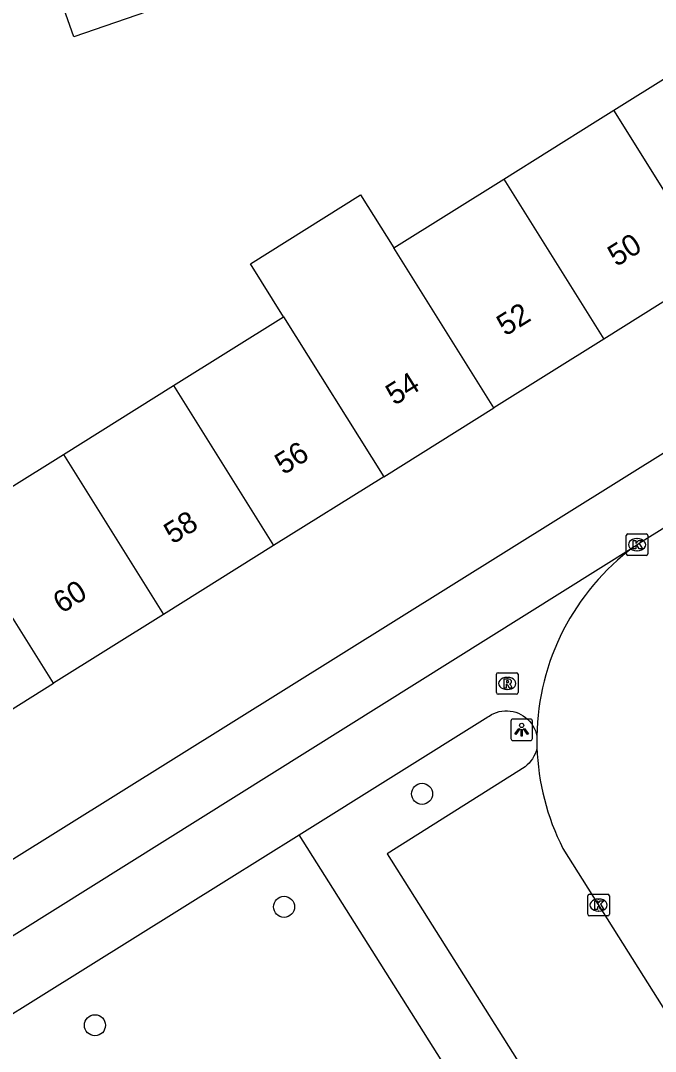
# Model space of a CAD drawing. Extents: x 160077 to 160945, y 386481 to 387498.
# Drawn here: x 160202.38 to 160231.86, y 387206.82 to 387254.7 of the extents above; entities that cross this region are included whole.
import ezdxf

# ---------------------------------------------------------------- set-up
doc = ezdxf.new("R2010")
doc.units = 0
for name, color, linetype in [('IMGEO_Boom', 7, 'Continuous'), ('IMGEO_Fietspad_open', 7, 'Continuous'), ('IMGEO_Kolk', 7, 'Continuous'), ('IMGEO_Lichtpunt', 7, 'Continuous'), ('IMGEO_Pand', 7, 'Continuous'), ('IMGEO_Pand_nummerreeks', 7, 'Continuous'), ('IMGEO_Rijbaan_lokaal_open', 7, 'Continuous'), ('IMGEO_Rioolput', 7, 'Continuous'), ('IMGEO_Voetpad_open', 7, 'Continuous')]:
    doc.layers.add(name, color=color, linetype=linetype)

msp = doc.modelspace()

# ---------------------------------------------------------------- linework, layer by layer
at = {"layer": 'IMGEO_Boom'}
for centre in [(160221.024, 387218.784), (160214.615, 387213.534), (160205.833, 387208.034)]:
    msp.add_circle(centre, 0.489, dxfattribs=at)
at = {"layer": 'IMGEO_Fietspad_open'}
for points in [[(160183.16, 387200.334), (160188.403, 387203.609), (160190.744, 387205.097), (160192.259, 387206.087), (160230.858, 387230.252)], [(160215.32, 387216.878), (160224.07, 387222.353), (160224.134, 387222.398), (160224.245, 387222.465), (160224.362, 387222.522), (160224.482, 387222.567), (160224.607, 387222.602), (160224.734, 387222.626), (160224.863, 387222.638), (160224.992, 387222.639), (160225.121, 387222.628), (160225.248, 387222.606), (160225.373, 387222.572), (160225.495, 387222.527), (160225.611, 387222.472), (160225.723, 387222.406), (160225.828, 387222.331), (160225.926, 387222.247), (160226.016, 387222.154), (160226.098, 387222.053), (160226.17, 387221.946), (160226.232, 387221.833), (160226.284, 387221.714), (160226.325, 387221.592), (160226.355, 387221.466)], [(160184.423, 387197.569), (160192.529, 387202.664), (160211.947, 387214.771), (160215.32, 387216.878)]]:
    msp.add_lwpolyline(points, dxfattribs=at)
at = {"layer": 'IMGEO_Kolk'}
for p, q in [((160230.582, 387230.858), (160231.434, 387230.858)), ((160230.507, 387229.932), (160230.507, 387230.784)), ((160230.995, 387230.638), (160231.02, 387230.638)), ((160231.508, 387230.784), (160231.508, 387229.932)), ((160231.434, 387229.858), (160230.582, 387229.858)), ((160231.018, 387230.078), (160230.993, 387230.078)), ((160228.72, 387213.19), (160228.72, 387214.042)), ((160228.795, 387214.116), (160229.647, 387214.116)), ((160229.721, 387214.042), (160229.721, 387213.19)), ((160229.208, 387213.896), (160229.233, 387213.896)), ((160229.647, 387213.116), (160228.795, 387213.116)), ((160229.231, 387213.336), (160229.206, 387213.336))]:
    msp.add_line(p, q, dxfattribs=at)
for points in [[(160230.582, 387230.858), (160231.434, 387230.858)], [(160230.507, 387229.932), (160230.507, 387230.784)], [(160230.828, 387230.558), (160230.951, 387230.558), (160230.951, 387230.407), (160231.081, 387230.558), (160231.245, 387230.558), (160231.099, 387230.407), (160231.252, 387230.158), (160231.1, 387230.158), (160231.015, 387230.322), (160230.951, 387230.255), (160230.951, 387230.158), (160230.828, 387230.158), (160230.828, 387230.558)], [(160231.508, 387230.784), (160231.508, 387229.932)], [(160231.434, 387229.858), (160230.582, 387229.858)], [(160228.72, 387213.19), (160228.72, 387214.042)], [(160228.795, 387214.116), (160229.647, 387214.116)], [(160229.721, 387214.042), (160229.721, 387213.19)], [(160229.041, 387213.816), (160229.164, 387213.816), (160229.164, 387213.665), (160229.294, 387213.816), (160229.458, 387213.816), (160229.312, 387213.665), (160229.465, 387213.416), (160229.313, 387213.416), (160229.228, 387213.58), (160229.164, 387213.513), (160229.164, 387213.416), (160229.041, 387213.416), (160229.041, 387213.816)], [(160229.647, 387213.116), (160228.795, 387213.116)]]:
    msp.add_lwpolyline(points, dxfattribs=at)
for centre, start, end in [((160230.584, 387230.782), 91.552, 178.448), ((160230.584, 387230.782), 91.552, 178.448), ((160231.432, 387230.782), 1.552, 88.448), ((160231.432, 387230.782), 1.552, 88.448), ((160230.584, 387229.934), 181.552, 268.448), ((160230.584, 387229.934), 181.552, 268.448), ((160231.432, 387229.934), 271.552, 358.448), ((160231.432, 387229.934), 271.552, 358.448), ((160228.797, 387214.04), 91.552, 178.448), ((160228.797, 387214.04), 91.552, 178.448), ((160229.645, 387214.04), 1.552, 88.448), ((160229.645, 387214.04), 1.552, 88.448), ((160228.797, 387213.192), 181.552, 268.448), ((160228.797, 387213.192), 181.552, 268.448), ((160229.645, 387213.192), 271.552, 358.448), ((160229.645, 387213.192), 271.552, 358.448)]:
    msp.add_arc(centre, 0.0765, start, end, dxfattribs=at)
for centre, major_axis, ratio, start_param, end_param in [((160230.994, 387230.358), (-0.387, 0.002), 0.722429, 4.712389, 7.853982), ((160231.019, 387230.358), (-0.39, 0.002), 0.717154, 1.570796, 4.712389), ((160229.207, 387213.616), (-0.387, 0.002), 0.722429, 4.712389, 7.853982), ((160229.232, 387213.616), (-0.39, 0.002), 0.717154, 1.570796, 4.712389)]:
    msp.add_ellipse(centre, major_axis=major_axis, ratio=ratio, start_param=start_param, end_param=end_param, dxfattribs=at)
at = {"layer": 'IMGEO_Lichtpunt'}
for p, q in [((160226.052, 387222.257), (160225.244, 387222.257)), ((160226.052, 387222.257), (160225.244, 387222.257)), ((160225.15, 387222.162), (160225.15, 387221.355)), ((160225.15, 387222.162), (160225.15, 387221.355)), ((160226.146, 387221.355), (160226.146, 387222.162)), ((160226.146, 387221.355), (160226.146, 387222.162)), ((160225.244, 387221.261), (160226.052, 387221.261)), ((160225.244, 387221.261), (160226.052, 387221.261))]:
    msp.add_line(p, q, dxfattribs=at)
for points in [[(160225.524, 387221.826), (160225.563, 387221.798), (160225.375, 387221.536), (160225.337, 387221.563), (160225.524, 387221.826)], [(160225.626, 387221.778), (160225.673, 387221.778), (160225.673, 387221.456), (160225.626, 387221.456), (160225.626, 387221.778)], [(160225.736, 387221.798), (160225.774, 387221.825), (160225.961, 387221.563), (160225.922, 387221.535), (160225.736, 387221.798)]]:
    msp.add_lwpolyline(points, dxfattribs=at)
msp.add_circle((160225.649, 387221.96), 0.0994, dxfattribs=at)
for centre, start, end in [((160225.244, 387222.162), 90, 180), ((160225.244, 387222.162), 90, 180), ((160226.052, 387222.162), 0, 90), ((160226.052, 387222.162), 0, 90), ((160225.244, 387221.355), 180, 270), ((160225.244, 387221.355), 180, 270), ((160226.052, 387221.355), 270, 0), ((160226.052, 387221.355), 270, 360)]:
    msp.add_arc(centre, 0.0946, start, end, dxfattribs=at)
at = {"layer": 'IMGEO_Pand'}
for points in [[(160208.715, 387255.288), (160204.855, 387253.942), (160204.036, 387256.29)], [(160229.929, 387250.541), (160235.042, 387253.739)], [(160224.817, 387247.344), (160229.064, 387250), (160229.929, 387250.541)], [(160234.579, 387243.107), (160230.268, 387250), (160229.929, 387250.541)], [(160219.705, 387244.147), (160224.817, 387247.344)], [(160224.817, 387247.344), (160229.466, 387239.91)], [(160214.592, 387240.949), (160213.055, 387243.407), (160218.168, 387246.605), (160219.705, 387244.147)], [(160224.355, 387236.713), (160219.705, 387244.147)], [(160234.579, 387243.107), (160229.466, 387239.91)], [(160209.48, 387237.751), (160214.592, 387240.949)], [(160214.592, 387240.949), (160219.242, 387233.515)], [(160229.466, 387239.91), (160224.355, 387236.713)], [(160204.367, 387234.554), (160209.48, 387237.751)], [(160209.48, 387237.751), (160214.129, 387230.317)], [(160219.242, 387233.515), (160224.355, 387236.713)], [(160199.255, 387231.356), (160204.367, 387234.554)], [(160204.367, 387234.554), (160209.017, 387227.119)], [(160219.242, 387233.515), (160214.129, 387230.317)], [(160203.904, 387223.922), (160199.255, 387231.356)], [(160214.129, 387230.317), (160209.017, 387227.119)], [(160209.017, 387227.119), (160203.904, 387223.922)], [(160198.595, 387220.601), (160203.904, 387223.922)]]:
    msp.add_lwpolyline(points, dxfattribs=at)
at = {"layer": 'IMGEO_Rijbaan_lokaal_open'}
for points in [[(160242.323, 387237.407), (160231.101, 387230.415), (160230.944, 387230.31), (160230.858, 387230.252)], [(160226.355, 387221.466), (160226.36, 387220.948)], [(160227.566, 387216.245), (160250.335, 387180.106), (160272.691, 387144.583)]]:
    msp.add_lwpolyline(points, dxfattribs=at)
for centre, radius, start, end in [((160237.513, 387221.294), 11.159, 126.6099, 179.118), ((160237.468, 387221.29), 11.114, 181.7657, 206.9994)]:
    msp.add_arc(centre, radius, start, end, dxfattribs=at)
at = {"layer": 'IMGEO_Rioolput'}
for p, q in [((160224.477, 387223.485), (160224.477, 387224.337)), ((160224.552, 387224.411), (160225.404, 387224.411)), ((160224.965, 387224.191), (160224.99, 387224.191)), ((160225.478, 387224.337), (160225.478, 387223.485)), ((160224.988, 387223.631), (160224.963, 387223.631)), ((160225.404, 387223.411), (160224.552, 387223.411))]:
    msp.add_line(p, q, dxfattribs=at)
for points in [[(160224.477, 387223.485), (160224.477, 387224.337)], [(160224.552, 387224.411), (160225.404, 387224.411)], [(160225.066, 387224.109), (160224.814, 387224.111), (160224.814, 387223.711)], [(160225.478, 387224.337), (160225.478, 387223.485)], [(160224.814, 387223.711), (160224.938, 387223.711), (160224.938, 387223.873), (160224.949, 387223.873)], [(160224.992, 387224.03), (160224.938, 387224.03), (160224.938, 387223.949)], [(160224.938, 387223.949), (160224.99, 387223.949)], [(160224.996, 387223.844), (160225.067, 387223.711), (160225.207, 387223.711), (160225.142, 387223.837)], [(160225.404, 387223.411), (160224.552, 387223.411)]]:
    msp.add_lwpolyline(points, dxfattribs=at)
for centre, radius, start, end in [((160224.554, 387224.335), 0.0765, 91.552, 178.448), ((160224.554, 387224.335), 0.0765, 91.552, 178.448), ((160225.065, 387223.999), 0.109, 350.3612, 89.416), ((160225.402, 387224.335), 0.0765, 1.552, 88.448), ((160225.402, 387224.335), 0.0765, 1.552, 88.448), ((160224.948, 387223.82), 0.0533, 26.0293, 88.6989), ((160224.974, 387224.138), 0.19, 274.7715, 282.9687), ((160224.998, 387223.934), 0.0964, 77.0061, 93.1865), ((160225.012, 387223.991), 0.0378, 276.6634, 79.6772), ((160225.063, 387223.999), 0.112, 277.5842, 350.9817), ((160225.047, 387223.784), 0.108, 29.5134, 73.7905), ((160224.554, 387223.487), 0.0765, 181.552, 268.448), ((160224.554, 387223.487), 0.0765, 181.552, 268.448), ((160225.402, 387223.487), 0.0765, 271.552, 358.448), ((160225.402, 387223.487), 0.0765, 271.552, 358.448)]:
    msp.add_arc(centre, radius, start, end, dxfattribs=at)
for centre, major_axis, ratio, start_param, end_param in [((160224.964, 387223.911), (-0.387, 0.002), 0.722429, 4.712389, 7.853982), ((160224.989, 387223.911), (-0.39, 0.002), 0.717154, 1.570796, 4.712389)]:
    msp.add_ellipse(centre, major_axis=major_axis, ratio=ratio, start_param=start_param, end_param=end_param, dxfattribs=at)
at = {"layer": 'IMGEO_Voetpad_open'}
for points in [[(160201.816, 387215.631), (160253.275, 387247.762)], [(160226.36, 387220.948), (160226.349, 387220.891), (160226.316, 387220.766), (160226.273, 387220.645), (160226.218, 387220.528), (160226.154, 387220.417), (160226.08, 387220.311), (160225.996, 387220.213), (160225.904, 387220.123), (160225.805, 387220.041), (160219.401, 387215.993), (160228.959, 387200.845)], [(160225.112, 387201.343), (160215.32, 387216.878)]]:
    msp.add_lwpolyline(points, dxfattribs=at)

# ---------------------------------------------------------------- texts
at = {"layer": 'IMGEO_Pand_nummerreeks'}
for s, rotation, p in [('50', 32.0243, (160230.049, 387243.246)), ('52', 32.0243, (160224.892, 387240.02)), ('54', 32.0226, (160219.742, 387236.8)), ('56', 32.0243, (160214.59, 387233.578)), ('58', 32.0243, (160209.441, 387230.356)), ('60', 32.0243, (160204.289, 387227.134))]:
    msp.add_text(s, height=1, rotation=rotation, dxfattribs=at).set_placement(p)

doc.saveas('drawing.dxf')
